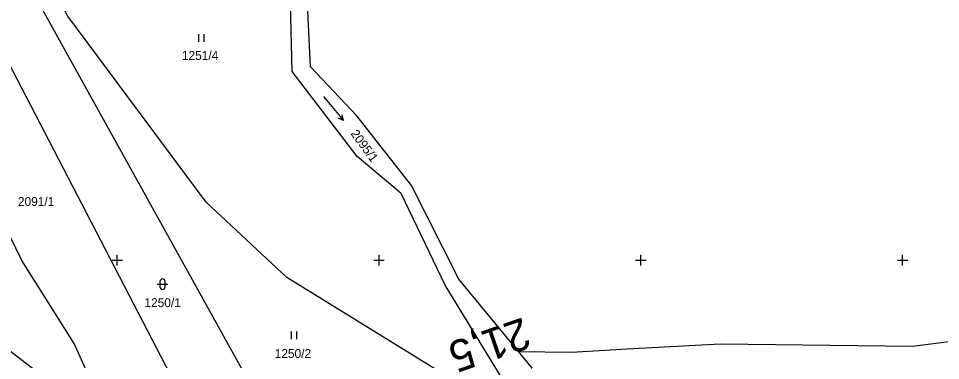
# Model space of a CAD drawing. Extents: x -776734 to -748832, y -1118122 to -976986.
# Drawn here: x -751218.9 to -751042.8, y -1114619.2 to -1114553.8 of the extents above; entities that cross this region are included whole.
import ezdxf

# ---------------------------------------------------------------- set-up
doc = ezdxf.new("R2010")
doc.units = 0
for name, color, linetype in [('KM_Hranice obce', 7, 'Continuous'), ('KM_Hranice parcel', 7, 'Continuous'), ('KM_Parcelní čísla', 7, 'Continuous'), ('KM_Značky kultur', 7, 'Continuous'), ('Level 61 Křížky', 7, 'Continuous'), ('OSA', 7, 'Continuous')]:
    doc.layers.add(name, color=color, linetype=linetype)

msp = doc.modelspace()

# ---------------------------------------------------------------- linework, layer by layer
at = {"layer": 'KM_Hranice obce'}
msp.add_line((-751109.85, -1114633.73), (-751123.4, -1114617.49), dxfattribs=at)
msp.add_line((-751109.85, -1114633.73), (-751123.4, -1114617.49), dxfattribs=at)
msp.add_lwpolyline([(-751123.4, -1114617.49), (-751134.76, -1114603.61), (-751143.79, -1114585.76), (-751154.22, -1114572.38), (-751163.11, -1114563.05), (-751163.77, -1114548.27), (-751162.87, -1114526.01), (-751162.13, -1114520.41), (-751158.41, -1114505.99)], dxfattribs=at)
msp.add_lwpolyline([(-751123.4, -1114617.49), (-751134.76, -1114603.61), (-751143.79, -1114585.76), (-751154.22, -1114572.38), (-751163.11, -1114563.05), (-751163.77, -1114548.27), (-751162.87, -1114526.01), (-751162.13, -1114520.41), (-751158.41, -1114505.99)], dxfattribs=at)
at = {"layer": 'KM_Hranice parcel'}
msp.add_line((-751200.87, -1114632.4), (-751233.34, -1114607.59), dxfattribs=at)
for points in [[(-751248.93, -1114484.17), (-751256.66, -1114493), (-751183.62, -1114634.05), (-751176.58, -1114650.88), (-751162.9, -1114674.22)], [(-751118.24, -1114633.81), (-751125.08, -1114624.94), (-751137.4, -1114604.78), (-751145.79, -1114587.23), (-751154.2, -1114580.18), (-751166.61, -1114563.91), (-751167.39, -1114532.51), (-751161.51, -1114503.66), (-751161.67, -1114499.9)], [(-751200.87, -1114632.4), (-751208.25, -1114615.92), (-751218.22, -1114600.09), (-751226.53, -1114583.17), (-751268.49, -1114506.51)], [(-751118.39, -1114659.47), (-751153.69, -1114640.78), (-751166.28, -1114630.46), (-751169.7, -1114632.51), (-751219.15, -1114543.3), (-751235.21, -1114511.41)], [(-751118.24, -1114633.81), (-751167.63, -1114603.32), (-751183.05, -1114588.89), (-751209.46, -1114553.38), (-751224.59, -1114524.12), (-751229.88, -1114510.58)], [(-751123.4, -1114617.49), (-751113.24, -1114617.58), (-751102.68, -1114616.94), (-751084.8, -1114616.01), (-751048.12, -1114616.42), (-751004.23, -1114610.82), (-750945.62, -1114595.97)]]:
    msp.add_lwpolyline(points, dxfattribs=at)
at = {"layer": 'KM_Značky kultur'}
for p, q in [((-751184.421, -1114558.28), (-751184.421, -1114556.78)), ((-751183.42, -1114558.28), (-751183.42, -1114556.78)), ((-751160.644, -1114568.691), (-751156.787, -1114573.287)), ((-751156.787, -1114573.287), (-751157.799, -1114572.861)), ((-751156.787, -1114573.287), (-751157.031, -1114572.216)), ((-751192.361, -1114604.601), (-751190.359, -1114604.601)), ((-751191.861, -1114604.101), (-751191.861, -1114605.102)), ((-751190.859, -1114605.102), (-751190.859, -1114604.101)), ((-751166.701, -1114615.11), (-751166.701, -1114613.61)), ((-751165.7, -1114615.11), (-751165.7, -1114613.61))]:
    msp.add_line(p, q, dxfattribs=at)
for centre, start, end in [((-751191.36, -1114604.1009), 0, 180), ((-751191.36, -1114605.1009), 180, 359.987886)]:
    msp.add_arc(centre, 0.5, start, end, dxfattribs=at)
at = {"layer": 'Level 61 Křížky'}
for p, q in [((-751200, -1114600), (-751200, -1114599)), ((-751150, -1114600), (-751150, -1114599)), ((-751100, -1114600), (-751100, -1114599)), ((-751050, -1114600), (-751050, -1114599)), ((-751201, -1114600), (-751199, -1114600)), ((-751200, -1114601), (-751200, -1114600)), ((-751151, -1114600), (-751149, -1114600)), ((-751150, -1114601), (-751150, -1114600)), ((-751101, -1114600), (-751099, -1114600)), ((-751100, -1114601), (-751100, -1114600)), ((-751051, -1114600), (-751049, -1114600)), ((-751050, -1114601), (-751050, -1114600))]:
    msp.add_line(p, q, dxfattribs=at)

# ---------------------------------------------------------------- texts
at = {"layer": 'KM_Parcelní čísla'}
for s, p in [('1251/4', (-751187.657, -1114561.71)), ('2091/1', (-751218.9798, -1114589.6447)), ('1250/1', (-751194.817, -1114608.98)), ('1250/2', (-751169.937, -1114618.7))]:
    msp.add_text(s, height=1.7, dxfattribs=at).set_placement(p)
msp.add_text('2095/1', height=1.7, rotation=306, dxfattribs=at).set_placement((-751155.5216, -1114575.8135))
at = {"layer": 'OSA'}
msp.add_text('21,5', height=6, rotation=199.034988, dxfattribs=at).set_placement((-751122.4708, -1114610.872))

doc.saveas('drawing.dxf')
